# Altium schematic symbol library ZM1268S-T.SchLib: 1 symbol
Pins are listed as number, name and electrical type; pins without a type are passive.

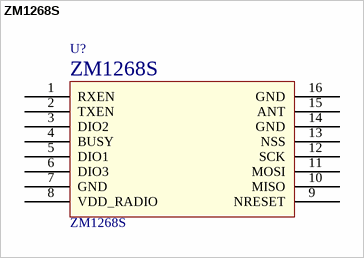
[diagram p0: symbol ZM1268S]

## ZM1268S
designator U?
footprint ZM1268S_REVA
footprint ZM1268S_REVB
pins: 1 RXEN, 2 TXEN, 3 DIO2, 4 BUSY, 5 DIO1, 6 DIO3, 7 GND, 8 VDD_RADIO, 9 NRESET, 10 MISO, 11 MOSI, 12 SCK, 13 NSS, 14 GND, 15 ANT, 16 GND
